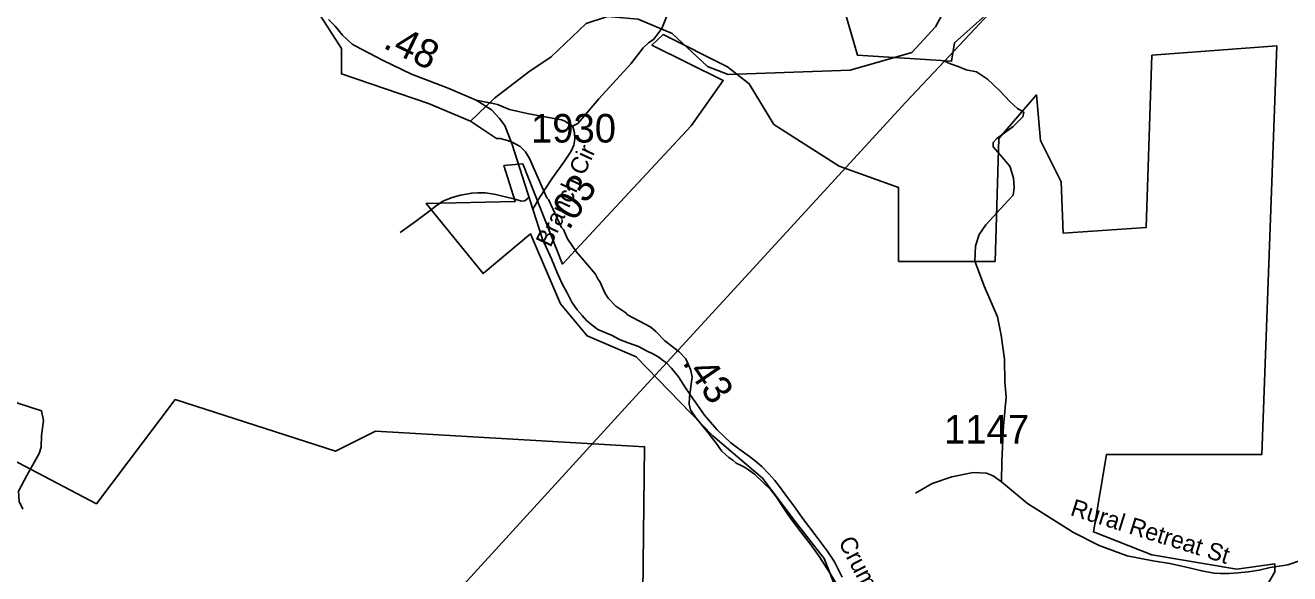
# Model space of a CAD drawing. Extents: x 1159738 to 1321356, y 736314 to 882035.
# Drawn here: x 1235163 to 1240691, y 776906 to 779304 of the extents above; entities that cross this region are included whole.
import ezdxf

# ---------------------------------------------------------------- set-up
doc = ezdxf.new("R2010")
doc.units = 0
for name, color, linetype in [('Exist Boundary Political City Limit New Hole', 7, 'Continuous'), ('Exist Boundary Political City Limit New InsideOut', 7, 'Continuous'), ('Exist Hydrographic Creek Single Shore', 7, 'Continuous'), ('Exist Hydrographic Misc Water Feature', 7, 'Continuous'), ('Exist Road Non-System Type 51', 7, 'Continuous'), ('Exist Road Secondary Mileage Hundredths English Label', 7, 'Continuous'), ('Exist Road Secondary Type 51 Attributed', 7, 'Continuous'), ('Exist Road Secondary Type 51 Label', 7, 'Continuous'), ('Exist Road Secondary Type 51 Number Label', 7, 'Continuous'), ('Exist Utilities Electrical Transmission Line', 7, 'Continuous')]:
    doc.layers.add(name, color=color, linetype=linetype)

msp = doc.modelspace()

# ---------------------------------------------------------------- linework, layer by layer
at = {"layer": 'Exist Boundary Political City Limit New Hole'}
for points in [[(1240460.2, 776926.2), (1240089, 776989), (1239832.6, 777088.3), (1239890.5, 777427.6), (1240568.6, 777427.6), (1240634.7, 779215), (1240089, 779173.6), (1240064.2, 778420.6), (1239700.3, 778395.8), (1239692.1, 778619.2), (1239601.1, 778801.2), (1239584.6, 778999.8), (1239419.2, 778809.5), (1239402.7, 778271.6), (1238980.9, 778271.6), (1238980.9, 778594.3), (1238721.3, 778688.5), (1238436, 778870.5), (1238328.5, 779048.4), (1238233.4, 779122.9), (1237952.3, 779263.6), (1237902.7, 779218.1), (1238214.8, 779062.9), (1238074.2, 778864.3), (1237512, 778260.3), (1237338.3, 778698.8), (1237255.6, 778690.6), (1237305.2, 778533.3), (1236916.6, 778525.1), (1237164.7, 778218.9), (1237371.4, 778392.7), (1237503.7, 778086.5), (1237619.5, 777945.8), (1237834.5, 777854.8), (1238168.8, 777508.4), (1238386.8, 777323.3), (1238539.8, 777120.6), (1238655.5, 776971.7), (1238734.1, 776773.1)], [(1239675, 775862), (1240063.3, 776411.5), (1240129.5, 776481.8), (1240230.8, 776568.7), (1240375.5, 776477.7), (1240625.6, 776914.2), (1240625.6, 776949.3), (1240460.2, 776926.2)]]:
    msp.add_lwpolyline(points, dxfattribs=at)
at = {"layer": 'Exist Boundary Political City Limit New InsideOut'}
for points in [[(1240116.6, 779957.2), (1240109.8, 780038.2), (1239894, 780024.7), (1239482.6, 779606.2), (1239496.1, 779471.3), (1239226.3, 779228.3), (1239212.8, 779147.3), (1238801.4, 779174.3), (1238680, 779592.7), (1238855.4, 779592.7), (1238841.9, 780031.4), (1238282.1, 780031.4)], [(1234976.7, 776889.7), (1234969.6, 777016.6), (1234940.6, 777111.9), (1234880.6, 777223.5), (1234814.7, 777313.9), (1234769.7, 777398.9), (1234761.6, 777488.8), (1234774.6, 777583.8), (1234792.9, 777678.7), (1234877.8, 777833), (1234968.9, 777745.3), (1234843.5, 777542.5), (1235474.7, 777212.1), (1235818.1, 777667.4), (1236519.5, 777441.3), (1236694, 777529.2), (1237870.5, 777461.3), (1237857, 776313.9)]]:
    msp.add_lwpolyline(points, dxfattribs=at)
at = {"layer": 'Exist Hydrographic Creek Single Shore'}
for points in [[(1237462.4, 779166.4), (1237616, 779312.3), (1237709, 779343.3), (1237842.1, 779330.7), (1237991.1, 779268.7), (1238145.1, 779124.4), (1238236, 779089.8), (1238770.1, 779108.6), (1239039.1, 779185.3), (1239142, 779298.1), (1239308, 779603.3), (1239480.1, 779780.5), (1239870.1, 780054.9), (1240014, 780117.7), (1240193, 780281.5), (1240343, 780583.8), (1240437, 780667.2), (1241388.1, 780365.8)], [(1235063.9, 779597.2), (1235645.3, 779462.8), (1236059.4, 779626.7), (1236227.9, 779515.8), (1236401.2, 779429.1), (1236545.7, 779202.6), (1236545.7, 779091.8), (1236926.1, 778961.7), (1237109.1, 778884.6), (1237215, 778985.8), (1237364.3, 779101.5), (1237462.4, 779166.4)]]:
    msp.add_lwpolyline(points, dxfattribs=at)
at = {"layer": 'Exist Hydrographic Misc Water Feature'}
for points in [[(1237109.1, 778884.6), (1237223.7, 778809.7), (1237239.7, 778809.4), (1237271.5, 778800.6), (1237295.2, 778791.9), (1237326.8, 778774.8), (1237350.2, 778750.5), (1237367.4, 778721.5), (1237443.1, 778550.1), (1237451, 778541.8), (1237507.8, 778419.9), (1237515.7, 778411.6), (1237534.5, 778371), (1237571.1, 778314.5), (1237656.6, 778215.9), (1237668, 778191.9), (1237675.8, 778183.5), (1237696.5, 778134.7), (1237712, 778110.6), (1237745.1, 778075.5), (1237788.4, 778046.7), (1237796.2, 778038.3), (1237898.8, 777983.8), (1237920.3, 777965.2), (1237959.4, 777924.3), (1238022, 777876.3), (1238051.4, 777845.3), (1238072.2, 777798.9), (1238079.4, 777766.8), (1238067.1, 777679.2), (1238066.2, 777647.2), (1238071.7, 777623.3), (1238092.8, 777590.1), (1238149.1, 777522.4), (1238187.7, 777471.6)], [(1238187.7, 777471.6), (1238199.4, 777453.3), (1238209.1, 777441.6), (1238224.7, 777426.6), (1238238.4, 777414.8), (1238256, 777402.1), (1238271.8, 777389.5), (1238289.5, 777381), (1238307.3, 777372.4), (1238325, 777360.5), (1238350.6, 777341.2), (1238389.7, 777304.3), (1238422.9, 777273.2), (1238448, 777240.7), (1238474.9, 777198.4), (1238498.1, 777163.4), (1238521.2, 777130.9), (1238548.4, 777095.9), (1238594.9, 777036.7), (1238635.4, 776980.1), (1238681.5, 776907), (1238714.2, 776853.8)]]:
    msp.add_lwpolyline(points, dxfattribs=at)
at = {"layer": 'Exist Road Non-System Type 51'}
for points in [[(1237556.1, 778863.5), (1237578.3, 778875.3), (1237605.7, 778905.4), (1237671, 778982.5), (1237810.6, 779135.1), (1237864.2, 779205.7), (1237887.5, 779227.4), (1237911.1, 779244.4), (1237946.2, 779290.9), (1237969.7, 779348.4)], [(1239182, 779148.1), (1239208.4, 779135.3), (1239241.5, 779123.8), (1239277, 779110.1), (1239321.9, 779100.9), (1239369.2, 779068.8), (1239423.6, 779018.3), (1239468.6, 778970.1), (1239500.5, 778940.3), (1239528.9, 778924.2), (1239524.2, 778903.6), (1239481.6, 778862.3), (1239410.6, 778809.5), (1239394.1, 778791.2), (1239394.1, 778772.8), (1239424.8, 778738.4), (1239467.4, 778687.9), (1239483.9, 778637.4), (1239486.3, 778593.8), (1239481.6, 778561.7), (1239443.7, 778520.4), (1239363.3, 778431), (1239333.8, 778389.7), (1239317.2, 778339.2), (1239314.8, 778272.6), (1239357.4, 778160.2), (1239414.2, 778029.5), (1239429.5, 777949.2), (1239443.7, 777843.6), (1239446.1, 777745), (1239450.8, 777678.4), (1239440.2, 777552.2), (1239433.1, 777398.5), (1239430.8, 777308.3)], [(1237556.1, 778863.5), (1237522.1, 778884.4), (1237507.7, 778891), (1237482.9, 778894.9), (1237443.7, 778902.7), (1237357.5, 778918.4), (1237280.4, 778935.4), (1237228.1, 778957.7), (1237202, 778964.2), (1237185, 778966.8), (1237134.6, 778976.4)], [(1237465.5, 778633.3), (1237520.8, 778710.5), (1237549.5, 778753.7), (1237561.3, 778779.8), (1237565.2, 778806), (1237563.9, 778833.4), (1237558.7, 778855.7), (1237556.1, 778863.5)], [(1237365.7, 778552.5), (1237347.7, 778536.9), (1237333.4, 778535.7), (1237299.8, 778545.3), (1237213.6, 778565.7), (1237174.1, 778571.7), (1237141.8, 778571.7), (1237115.4, 778570.5), (1237066.3, 778560.9), (1237029.2, 778551.3), (1236988.5, 778534.5), (1236959.7, 778514.2), (1236933.4, 778493.8), (1236868.7, 778445.9), (1236801.7, 778397.9)], [(1234661.7, 778189.2), (1234689.2, 778169.9), (1234717.4, 778138.8), (1234748.6, 778082.2), (1234802.3, 777980.3), (1234839.1, 777915.2), (1234839.1, 777892.6), (1234870.2, 777881.2), (1234915.4, 777838.8), (1234994.6, 777751), (1235048.4, 777700.1), (1235130.4, 777652), (1235235, 777618), (1235243.5, 777575.6), (1235235, 777510.5), (1235232.2, 777459.5), (1235223.7, 777431.2), (1235170, 777335), (1235133.2, 777267.1), (1235136, 777221.8), (1235153, 777187.8)]]:
    msp.add_lwpolyline(points, dxfattribs=at)
at = {"layer": 'Exist Road Secondary Type 51 Attributed'}
for points in [[(1237381.9, 778499.6), (1237292.3, 778783.6), (1237260, 778866.4), (1237236.1, 778896.3), (1237201.5, 778934.6), (1237134.6, 778976.4), (1237012.7, 779029), (1236851.8, 779090.1), (1236728.6, 779150.1), (1236605.6, 779213.9), (1236592.6, 779221.8), (1236550.2, 779261.8), (1236517.9, 779300.6), (1236489.2, 779330.2)], [(1237381.9, 778499.6), (1237412.4, 778552.6), (1237465.5, 778633.3)], [(1238734.8, 776890.3), (1238701.3, 776958.1), (1238668.5, 777005.9), (1238616.8, 777076.6), (1238566.1, 777143.3), (1238518.3, 777209), (1238490.5, 777244.8), (1238464.6, 777281.7), (1238440.7, 777313.5), (1238413.9, 777342.4), (1238383, 777375.2), (1238356.2, 777398.1), (1238329.3, 777419), (1238283.5, 777451.9), (1238247.7, 777478.8), (1238220.9, 777502.7), (1238188, 777534.5), (1238158.2, 777568.4), (1238132.3, 777599.2), (1238081.6, 777671.9), (1238049.8, 777718.7), (1238018.9, 777767.5), (1237988.1, 777805.3), (1237967.2, 777828.2), (1237949.3, 777839.1), (1237933.4, 777853.1), (1237907.5, 777868), (1237879.7, 777880.9), (1237843.9, 777898.9), (1237799.1, 777915.8), (1237761.3, 777929.7), (1237725.5, 777948.6), (1237694.6, 777961.6), (1237665.8, 777974.5), (1237640.9, 777992.4), (1237617, 778013.5), (1237597.2, 778035.2), (1237576.3, 778060.1), (1237553.4, 778094), (1237530.5, 778137.8), (1237510.4, 778174.1), (1237486.5, 778226), (1237463.5, 778282.7), (1237424.6, 778369.5), (1237381.9, 778499.6)], [(1240625.6, 776935.9), (1240605.2, 776932.9), (1240557.9, 776921.6), (1240509.3, 776914.3), (1240464.8, 776910.4), (1240426.5, 776907.4), (1240389, 776906.3), (1240358.9, 776908.3), (1240306.2, 776918.3), (1240232.9, 776935.6), (1240167.4, 776950.9), (1240092.1, 776962.2), (1239981.1, 776983.4), (1239857.6, 777029.1), (1239746.5, 777086.5), (1239628.2, 777159.9), (1239545.4, 777212.7), (1239430.8, 777308.3), (1239394.1, 777334.3), (1239365.7, 777345.7), (1239306.6, 777348), (1239214.3, 777329.7), (1239128, 777299.9), (1239054.7, 777258.6)], [(1240752.6, 776967.4), (1240738.2, 776963.3), (1240683, 776944.1), (1240625.6, 776935.9)]]:
    msp.add_lwpolyline(points, dxfattribs=at)
at = {"layer": 'Exist Utilities Electrical Transmission Line'}
for points in [[(1239182, 779148.1), (1240004.8, 780027.4), (1240550.9, 780604.7), (1240869.9, 780979.7), (1241148.5, 781272.1), (1241557.1, 781670.1), (1241596.4, 781717.3)], [(1237953.9, 777814.2), (1239013.3, 778967.8), (1239182, 779148.1)], [(1233989.6, 773534.9), (1235380.3, 775003.3), (1237002.8, 776774.5), (1237816.5, 777664.6), (1237953.9, 777814.2)]]:
    msp.add_lwpolyline(points, dxfattribs=at)

# ---------------------------------------------------------------- texts
at = {"layer": 'Exist Road Secondary Mileage Hundredths English Label'}
for s, rotation, p in [('.48', 334.0329, (1236722.8, 779207.7)), ('.03', 56.6633, (1237539.1, 778403.7)), ('.43', 304.23, (1238033.6, 777829.9))]:
    msp.add_text(s, height=125, rotation=rotation, dxfattribs=at).set_placement(p)
at = {"layer": 'Exist Road Secondary Type 51 Label'}
for s, rotation, p in [('Branch Cir', 65.0997, (1237459.9, 778329.7)), ('Rural Retreat St', 342.6232, (1239727.8, 777162.8)), ('Crump Rd', 297.4932, (1238716.1, 777045.4))]:
    msp.add_text(s, height=75, rotation=rotation, dxfattribs=at).set_placement(p)
at = {"layer": 'Exist Road Secondary Type 51 Number Label'}
for s, p in [('1930', (1237374.2, 778791.5)), ('1147', (1239180.1, 777475.1))]:
    msp.add_text(s, height=125, dxfattribs=at).set_placement(p)

doc.saveas('drawing.dxf')
